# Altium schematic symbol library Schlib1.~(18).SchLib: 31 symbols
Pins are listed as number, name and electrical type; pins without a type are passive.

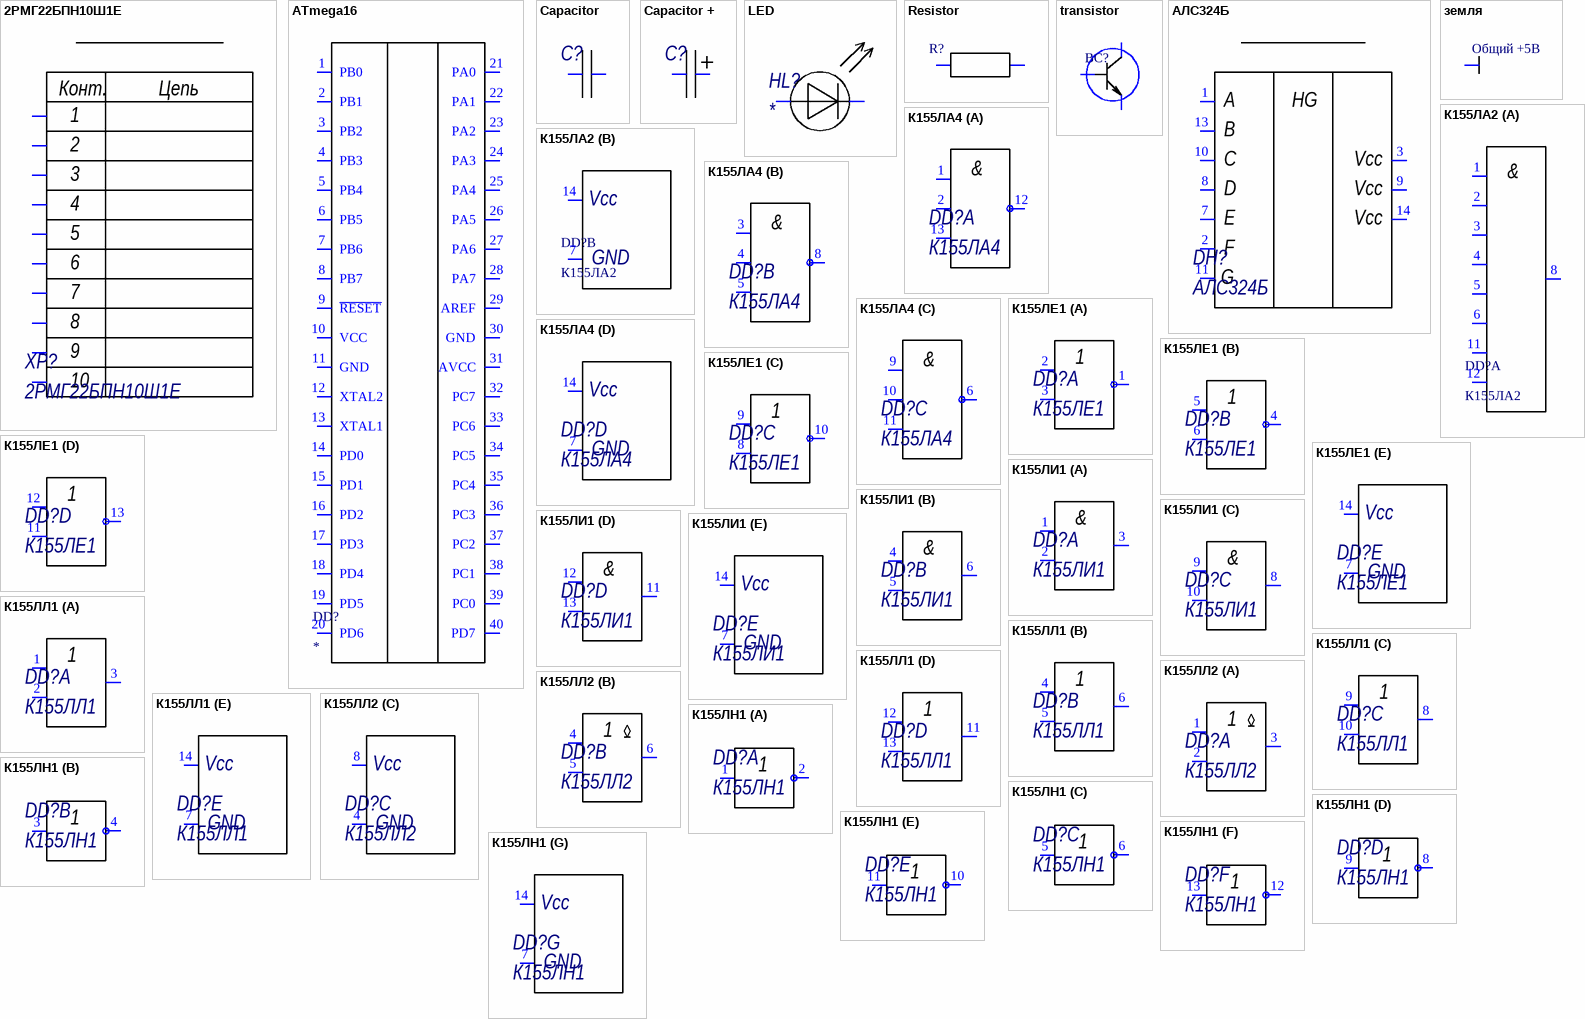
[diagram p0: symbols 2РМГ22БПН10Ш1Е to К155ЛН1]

## 2РМГ22БПН10Ш1Е
designator XP?
pins: 1, 1, 1, 1, 1, 1, 1, 1, 1, 1

## ATmega16
designator DD?
pins: 1 PB0, 2 PB1, 3 PB2, 4 PB3, 5 PB4, 6 PB5, 7 PB6, 8 PB7, 9 ~{RESET}, 10 VCC, 11 GND, 12 XTAL2, 13 XTAL1, 14 PD0, 15 PD1, 16 PD2, 17 PD3, 18 PD4, 19 PD5, 20 PD6, 21 PA0, 22 PA1, 23 PA2, 24 PA3, 25 PA4, 26 PA5, 27 PA6, 28 PA7, 29 AREF, 30 GND, 31 AVCC, 32 PC7, 33 PC6, 34 PC5, 35 PC4, 36 PC3, 37 PC2, 38 PC1, 39 PC0, 40 PD7

## Capacitor
designator C?  (value not drawn)
pins: 1, 2

## Capacitor +
designator C?  (value not drawn)
pins: 1, 2

## LED
designator HL?
pins: 1, 2

## Resistor
designator R?  (value not drawn)
pins: 1, 2

## transistor
designator BC?
pins: 1, 2, 2

## АЛС324Б
designator DH?
pins: 1, 2, 3, 7, 8, 9, 10, 11, 13, 14

## земля
designator Общий +5В
pins: 1

## К155ЛА2
designator DD?
part A pins: 1, 2, 3, 4, 5, 6, 8, 11, 12
part B pins: 7, 14

## К155ЛА4
designator DD?
part A pins: 1, 2, 12, 13
part B pins: 3, 4, 5, 8
part C pins: 6, 9, 10, 11
part D pins: 7, 14

## К155ЛЕ1
designator DD?
part A pins: 1, 2, 3
part B pins: 4, 5, 6
part C pins: 8, 9, 10
part D pins: 11, 12, 13
part E pins: 7, 14

## К155ЛИ1
designator DD?
part A pins: 1, 2, 3
part B pins: 4, 5, 6
part C pins: 8, 9, 10
part D pins: 11, 12, 13
part E pins: 7, 14

## К155ЛЛ1
designator DD?
part A pins: 1, 2, 3
part B pins: 4, 5, 6
part C pins: 8, 9, 10
part D pins: 11, 12, 13
part E pins: 7, 14

## К155ЛЛ2
designator DD?
part A pins: 1, 2, 3
part B pins: 4, 5, 6
part C pins: 4, 8

## К155ЛН1
designator DD?
part A pins: 1, 2
part B pins: 3, 4
part C pins: 5, 6
part D pins: 8, 9
part E pins: 10, 11
part F pins: 12, 13
part G pins: 7, 14

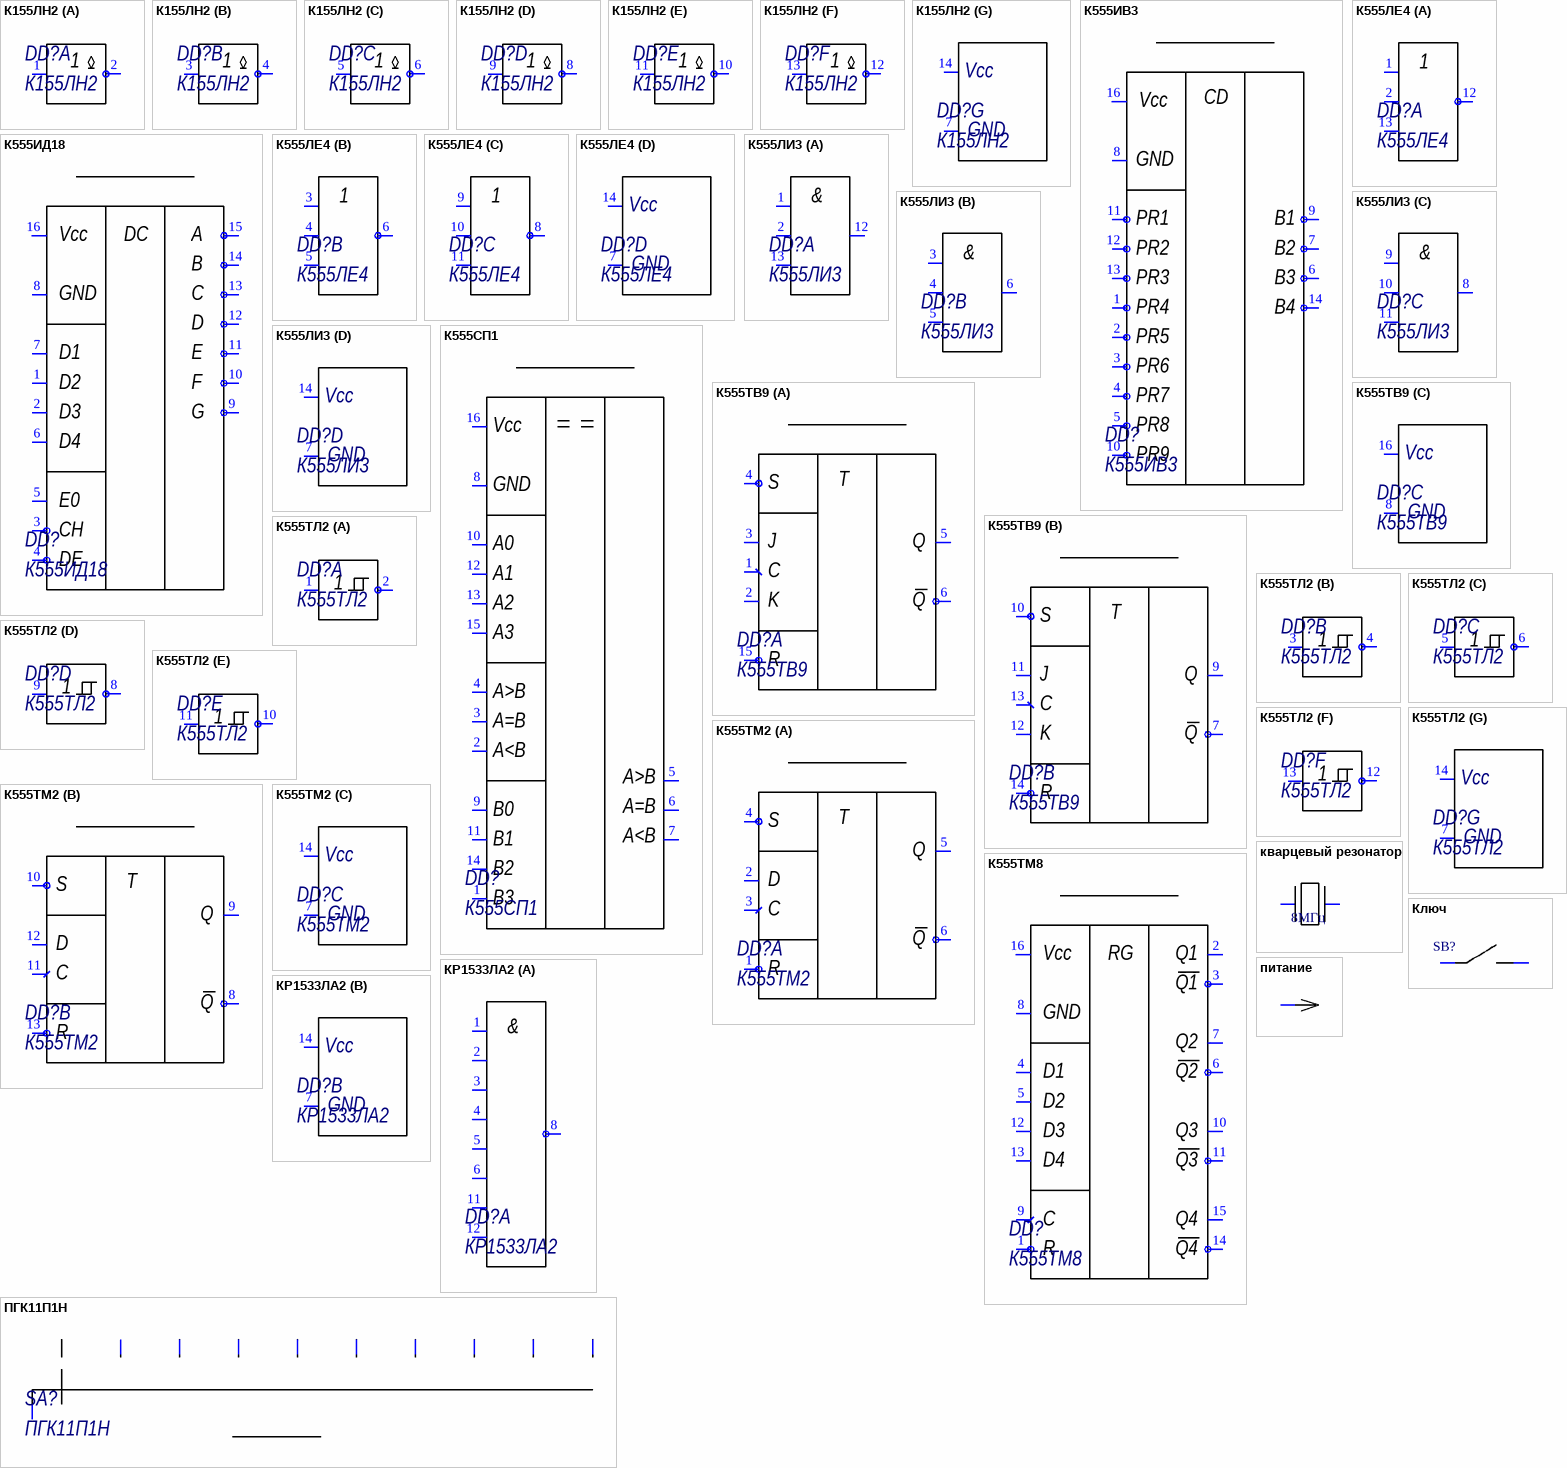
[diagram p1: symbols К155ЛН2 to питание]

## К155ЛН2
designator DD?
part A pins: 1, 2
part B pins: 3, 4
part C pins: 5, 6
part D pins: 8, 9
part E pins: 10, 11
part F pins: 12, 13
part G pins: 7, 14

## К555ИВ3
designator DD?
pins: 1, 2, 3, 4, 5, 6, 7, 8, 9, 10, 11, 12 ш, 13, 14, 16

## К555ИД18
designator DD?
pins: 1, 2, 3, 4, 5, 6, 7, 8, 9, 10, 11, 12, 13, 14, 15, 16

## К555ЛЕ4
designator DD?
part A pins: 1, 2, 12, 13
part B pins: 3, 4, 5, 6
part C pins: 8, 9, 10, 11
part D pins: 7, 14

## К555ЛИ3
designator DD?
part A pins: 1, 2, 12, 13
part B pins: 3, 4, 5, 6
part C pins: 8, 9, 10, 11
part D pins: 7, 14

## К555СП1
designator DD?
pins: 1, 2, 3, 4, 5, 6, 7, 8, 9, 10, 11, 12, 13, 14, 15, 16

## К555ТВ9
designator DD?
part A pins: 1, 2, 3, 4, 5, 6, 15
part B pins: 7, 9, 10, 11, 12, 13, 14
part C pins: 8, 16

## К555ТЛ2
designator DD?
part A pins: 1, 2
part B pins: 3, 4
part C pins: 5, 6
part D pins: 8, 9
part E pins: 10, 11
part F pins: 12, 13
part G pins: 7, 14

## К555ТМ2
designator DD?
part A pins: 1, 2, 3, 4, 5, 6
part B pins: 8, 9, 10, 11, 12, 13
part C pins: 7, 14

## К555ТМ8
designator DD?
pins: 1, 2, 3, 4, 5, 6, 7, 8, 9, 10, 11, 12, 13, 14, 15, 16

## кварцевый резонатор
designator ?, comment 8МГц
pins: 1, 2

## Ключ
designator SB?  (value not drawn)
pins: 1, 2

## КР1533ЛА2
designator DD?
part A pins: 1, 2, 3, 4, 5, 6, 8, 11, 12
part B pins: 7, 14

## ПГК11П1Н
designator SA?
pins: 1, 2, 2, 3, 4, 5, 6, 7, 8, 9

## питание
designator +5В, comment +5В  (value not drawn)
pins: 1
